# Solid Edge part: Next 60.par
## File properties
Title: Next 60 40x40 cm
Author: s.pallini
Template: Normal.par
Last saved by: s.pallini
Revision: 9
Application: Solid Edge
Tipo di contenuto documento: 0
Precisione: 0,990
Document Number: 8307
Revision: 0
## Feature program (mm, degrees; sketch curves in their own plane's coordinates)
sketch for "unnamed Protrusion 1" plane through (0, 0, 0) normal (0, 0, 1) x-axis (1, 0, 0)
  line (-200, -203.5) -> (200, -203.5)
  arc centre (200, -103.5) radius 100 from (200, -203.5) to (300, -103.5) ccw
  line (300, -103.5) -> (300, 103.5)
  arc centre (200, 103.5) radius 100 from (200, 203.5) to (300, 103.5) cw
  line (200, 203.5) -> (-200, 203.5)
  arc centre (-200, 103.5) radius 100 from (-200, 203.5) to (-300, 103.5) ccw
  line (-300, 103.5) -> (-300, -103.5)
  arc centre (-200, -103.5) radius 100 from (-300, -103.5) to (-200, -203.5) ccw
  dimension (linear) = 300
extrude "unnamed Protrusion 1" add finite 55 along -normal
sketch for "ExtrudedProtrusion_2" plane through (0, 0, 0) normal (0, 0, 1) x-axis (1, 0, 0)
  line (-170, -184.5) -> (170, -184.5)
  arc centre (170, -94.5) radius 90 from (260, -94.5) to (170, -184.5) cw
  line (260, -94.5) -> (260, 94.5)
  arc centre (170, 94.5) radius 90 from (170, 184.5) to (260, 94.5) cw
  line (170, 184.5) -> (-170, 184.5)
  arc centre (-170, 94.5) radius 90 from (-170, 184.5) to (-260, 94.5) ccw
  line (-260, 94.5) -> (-260, -94.5)
  arc centre (-170, -94.5) radius 90 from (-260, -94.5) to (-170, -184.5) ccw
  dimension (linear) = 260
extrude "ExtrudedProtrusion_2" add finite 133 along -normal
sketch for "ExtrudedCutout_1" plane through (0, 0, 0) normal (0, 0, 1) x-axis (1, 0, 0)
  line (-208.5, -162) -> (208.5, -162)
  arc centre (208.5, -112) radius 50 from (258.5, -112) to (208.5, -162) cw
  line (258.5, -112) -> (258.5, 112)
  arc centre (208.5, 112) radius 50 from (208.5, 162) to (258.5, 112) cw
  line (208.5, 162) -> (-208.5, 162)
  arc centre (-208.5, 112) radius 50 from (-208.5, 162) to (-258.5, 112) ccw
  line (-258.5, 112) -> (-258.5, -112)
  arc centre (-208.5, -112) radius 50 from (-258.5, -112) to (-208.5, -162) ccw
  dimension (linear) = 258.5
extrude "ExtrudedCutout_1" cut finite 100 along -normal  DraftAngle = 10 deg
fillet "Rotondo_1" radius 30
sketch for "Foro_1" plane through (0, 0, -100) normal (0, 0, 1) x-axis (1, 0, 0)
  hole centre (0, 0) bore radius 25
hole "Foro_1" diameter 50 through
fillet "Rotondo_2" radius 15
sketch for "ExtrudedCutout_2" #1 plane through (0, 0, -133) normal (0, 0, -1) x-axis (0, -1, 0)
  circle centre (0, 0) radius 35
sketch for "ExtrudedCutout_2" #2 plane through (0, 0, -133) normal (0, 0, -1) x-axis (0, -1, 0)
  line (-100, -220.5) -> (100, -220.5)
  arc centre (100, -175.5) radius 45 from (100, -220.5) to (145, -175.5) ccw
  line (145, -175.5) -> (145, 175.5)
  arc centre (100, 175.5) radius 45 from (100, 220.5) to (145, 175.5) cw
  line (100, 220.5) -> (-100, 220.5)
  arc centre (-100, 175.5) radius 45 from (-100, 220.5) to (-145, 175.5) ccw
  line (-145, 175.5) -> (-145, -175.5)
  arc centre (-100, -175.5) radius 45 from (-145, -175.5) to (-100, -220.5) ccw
  dimension (linear) = 100
extrude "ExtrudedCutout_2" cut finite 22 along -normal  DraftAngle = 20 deg
fillet "Rotondo_4" radius 10
sketch for "ExtrudedCutout_3" #1 plane through (0, 0, -55) normal (0, 0, -1) x-axis (0, 1, 0)
  line (-191.5, 178) -> (-191.5, -178)
  arc centre (-102.5, -178) radius 89 from (-191.5, -178) to (-102.5, -267) ccw
  line (-102.5, -267) -> (102.5, -267)
  arc centre (102.5, -178) radius 89 from (102.5, -267) to (191.5, -178) ccw
  line (191.5, 178) -> (191.5, -178)
  arc centre (102.5, 178) radius 89 from (102.5, 267) to (191.5, 178) cw
  line (-102.5, 267) -> (102.5, 267)
  arc centre (-102.5, 178) radius 89 from (-191.5, 178) to (-102.5, 267) cw
sketch for "ExtrudedCutout_3" #2 plane through (0, 0, -55) normal (0, 0, -1) x-axis (0, 1, 0)
  line (-185.5, 172) -> (-185.5, -172)
  arc centre (-96.5, -172) radius 89 from (-185.5, -172) to (-96.5, -261) ccw
  line (-96.5, -261) -> (96.5, -261)
  arc centre (96.5, -172) radius 89 from (96.5, -261) to (185.5, -172) ccw
  line (185.5, 172) -> (185.5, -172)
  arc centre (96.5, 172) radius 89 from (96.5, 261) to (185.5, 172) cw
  line (-96.5, 261) -> (96.5, 261)
  arc centre (-96.5, 172) radius 89 from (-185.5, 172) to (-96.5, 261) cw
extrude "ExtrudedCutout_3" cut finite 10 along -normal
fillet "Rotondo_5" radius 5
sketch for "Foro_2" plane through (0, 0, -55) normal (0, 0, -1) x-axis (-1, 0, 0)
  hole centre (-267, 96.5) bore radius 5
hole "Foro_2" diameter 10 finite
fillet "Rotondo_3" radius 10
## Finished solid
Body 1: solid body, 144 faces, 319 edges, 180 vertices.
  Faces by surface: cylinder 55, torus 35, plane 33, blend 12, cone 9
  Edges by curve: circle 165, line 140, intersection 14
Bounding box of the edges (mm; curved faces can reach further): 600.000 x 407.000 x 133.000, from (-300, -203.5, -133) to (300, 203.5, 0).
Cylindrical faces by radius (mm): R5 x10, R10 x24, R25 x1, R30 x4, R89 x8, R90 x4, R100 x4
Conical faces (half-angle, radius in mm at the cone's reference point): 10 deg R50 x4, 20 deg R35 x1, 20 deg R45 x4
Toroidal faces (ring radius, tube radius in mm): R7.1943 r30 x4, R27.9979 r10 x1, R29.9906 r10 x4, R40 r15 x1, R50.0094 r10 x1, R52.0021 r10 x4, R58.391 r10 x4, R80 r10 x4, R84 r5 x4, R90 r10 x8
Planar faces by outward normal: +x 4, +y 4, +z 2, -x 5, -y 4, -z 6, oblique 8
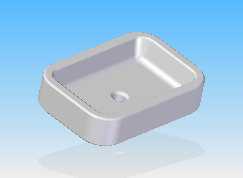
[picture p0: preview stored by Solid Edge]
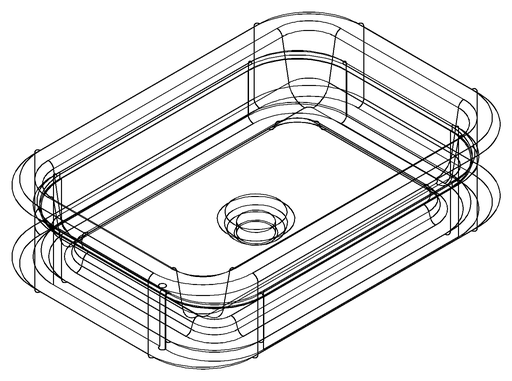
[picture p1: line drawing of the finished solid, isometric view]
